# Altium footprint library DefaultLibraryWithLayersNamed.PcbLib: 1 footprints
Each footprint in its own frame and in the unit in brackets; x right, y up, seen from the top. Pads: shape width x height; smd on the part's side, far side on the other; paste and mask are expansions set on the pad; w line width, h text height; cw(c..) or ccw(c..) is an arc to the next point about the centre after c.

## PCBComponent_1 [mm]
M5 Assembly Top:
  text ".Designator" at -1.8,-0.514 h1.02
